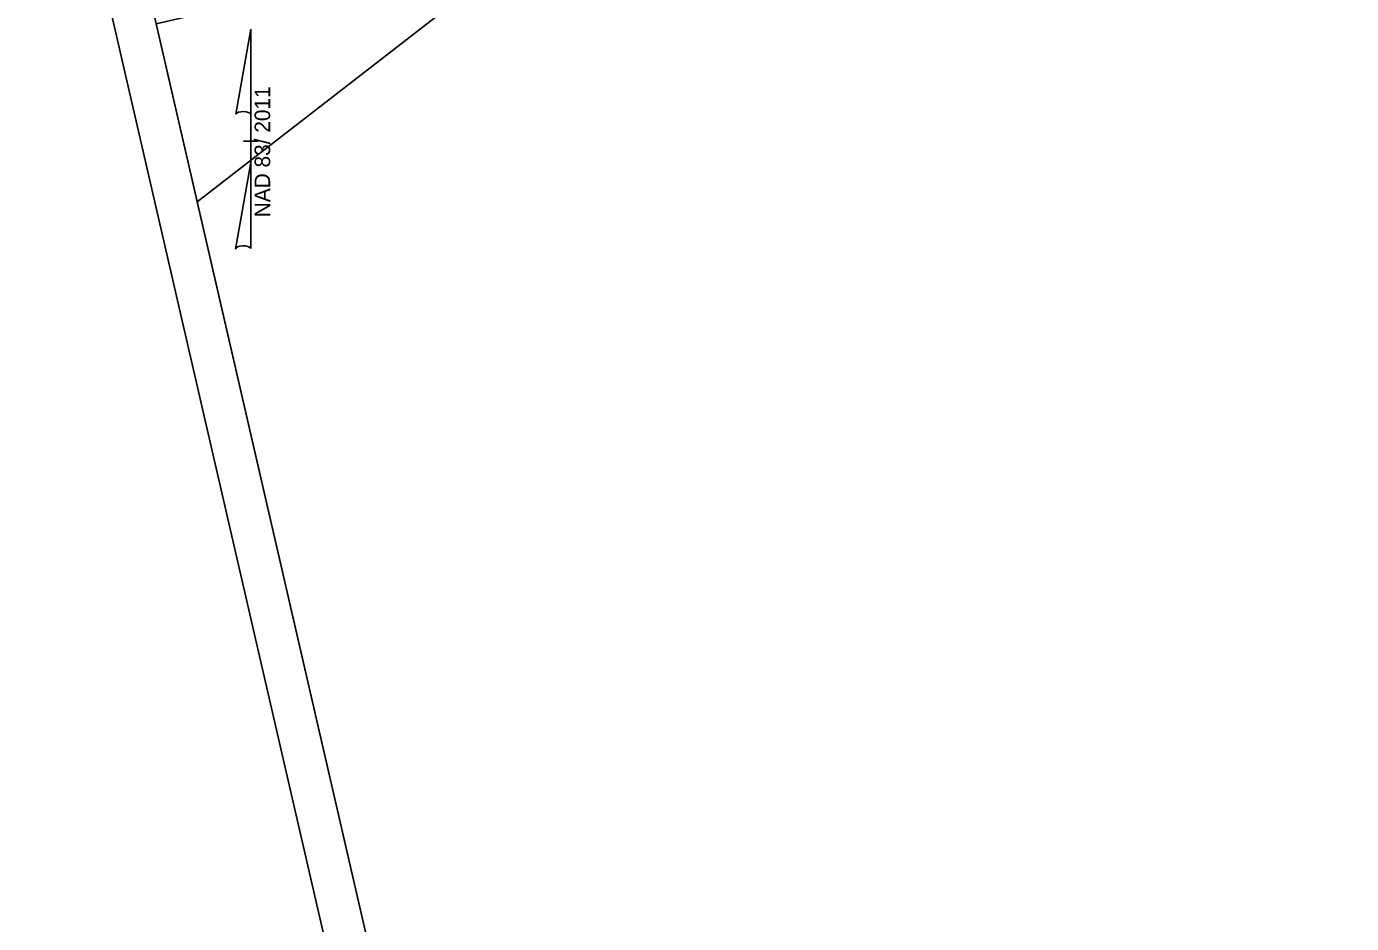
# Model space of a CAD drawing. Extents: x 480532 to 481977, y 491295 to 493182.
# Drawn here: x 480532 to 481255, y 492238 to 492728 of the extents above; entities that cross this region are included whole.
import ezdxf

# ---------------------------------------------------------------- set-up
doc = ezdxf.new("R2010")
doc.units = 0
for name, color, linetype in [('Prop North Arrow NAD83 for Plan Sheets CELL', 7, 'Continuous'), ('Sheet Clip Boundary CELL', 7, 'Continuous'), ('Sheet Plan CELL', 7, 'Continuous'), ('Sheet Plot Border Outside CELL', 7, 'Continuous')]:
    doc.layers.add(name, color=color, linetype=linetype)

msp = doc.modelspace()

# ---------------------------------------------------------------- linework, layer by layer
at = {"layer": 'Prop North Arrow NAD83 for Plan Sheets CELL'}
for p, q in [((480646.34, 492679.78), (480654.54, 492726.13)), ((480654.59, 492726.13), (480654.54, 492726.13)), ((480654.59, 492726.13), (480654.54, 492726.13)), ((480654.59, 492726.13), (480654.59, 492678.33)), ((480654.59, 492653.53), (480654.59, 492679.73)), ((480654.59, 492678.33), (480654.59, 492679.68)), ((480650.59, 492665.13), (480650.54, 492665.13)), ((480654.14, 492665.13), (480650.59, 492665.13)), ((480650.64, 492665.13), (480658.64, 492665.13)), ((480654.59, 492653.53), (480646.24, 492606.28)), ((480654.64, 492606.48), (480654.59, 492653.53))]:
    msp.add_line(p, q, dxfattribs=at)
for centre, start_param, end_param in [((480650.48, 492679.29), 0.216388, 2.908219), ((480650.48, 492606.12), 0.201328, 3.141593)]:
    msp.add_ellipse(centre, major_axis=(4.23, -0.03), ratio=0.461098, start_param=start_param, end_param=end_param, dxfattribs=at)
at = {"layer": 'Sheet Clip Boundary CELL'}
msp.add_lwpolyline([(481665.81, 492792.61), (481626.56, 492783.56), (481580.19, 492984.73), (481541.46, 492975.8), (481503.15, 493142.01), (481251.06, 493083.9), (481239.38, 493081.2), (480865.41, 492806.9), (480812.74, 492777.39), (480745.44, 492725.05), (480625.28, 492631.99), (480625.28, 492631.99), (480625.28, 492631.99), (480625.28, 492631.99), (480625.28, 492631.99), (480869.3, 491573.57), (481898.91, 491781.39)], close=True, dxfattribs=at)
at = {"layer": 'Sheet Plan CELL'}
for points in [[(480557.95, 492924.14), (480894.9, 491462.44), (481918.07, 491698.3), (481581.12, 493159.98)], [(481918.07, 491698.3), (480894.93, 491462.42), (480602.88, 492729.18), (480749.1, 492762.9), (480704.18, 492957.83), (481581.12, 493159.98)]]:
    msp.add_lwpolyline(points, close=True, dxfattribs=at)
at = {"layer": 'Sheet Plot Border Outside CELL'}
msp.add_lwpolyline([(481977.4, 491541.13), (481599.24, 493181.6), (480532.22, 492935.63), (480910.39, 491295.16)], close=True, dxfattribs=at)

# ---------------------------------------------------------------- texts
at = {"layer": 'Prop North Arrow NAD83 for Plan Sheets CELL'}
msp.add_text('NAD 83/ 2011', height=8.5, rotation=90, dxfattribs=at).set_placement((480665.11, 492623.61))

doc.saveas('drawing.dxf')
